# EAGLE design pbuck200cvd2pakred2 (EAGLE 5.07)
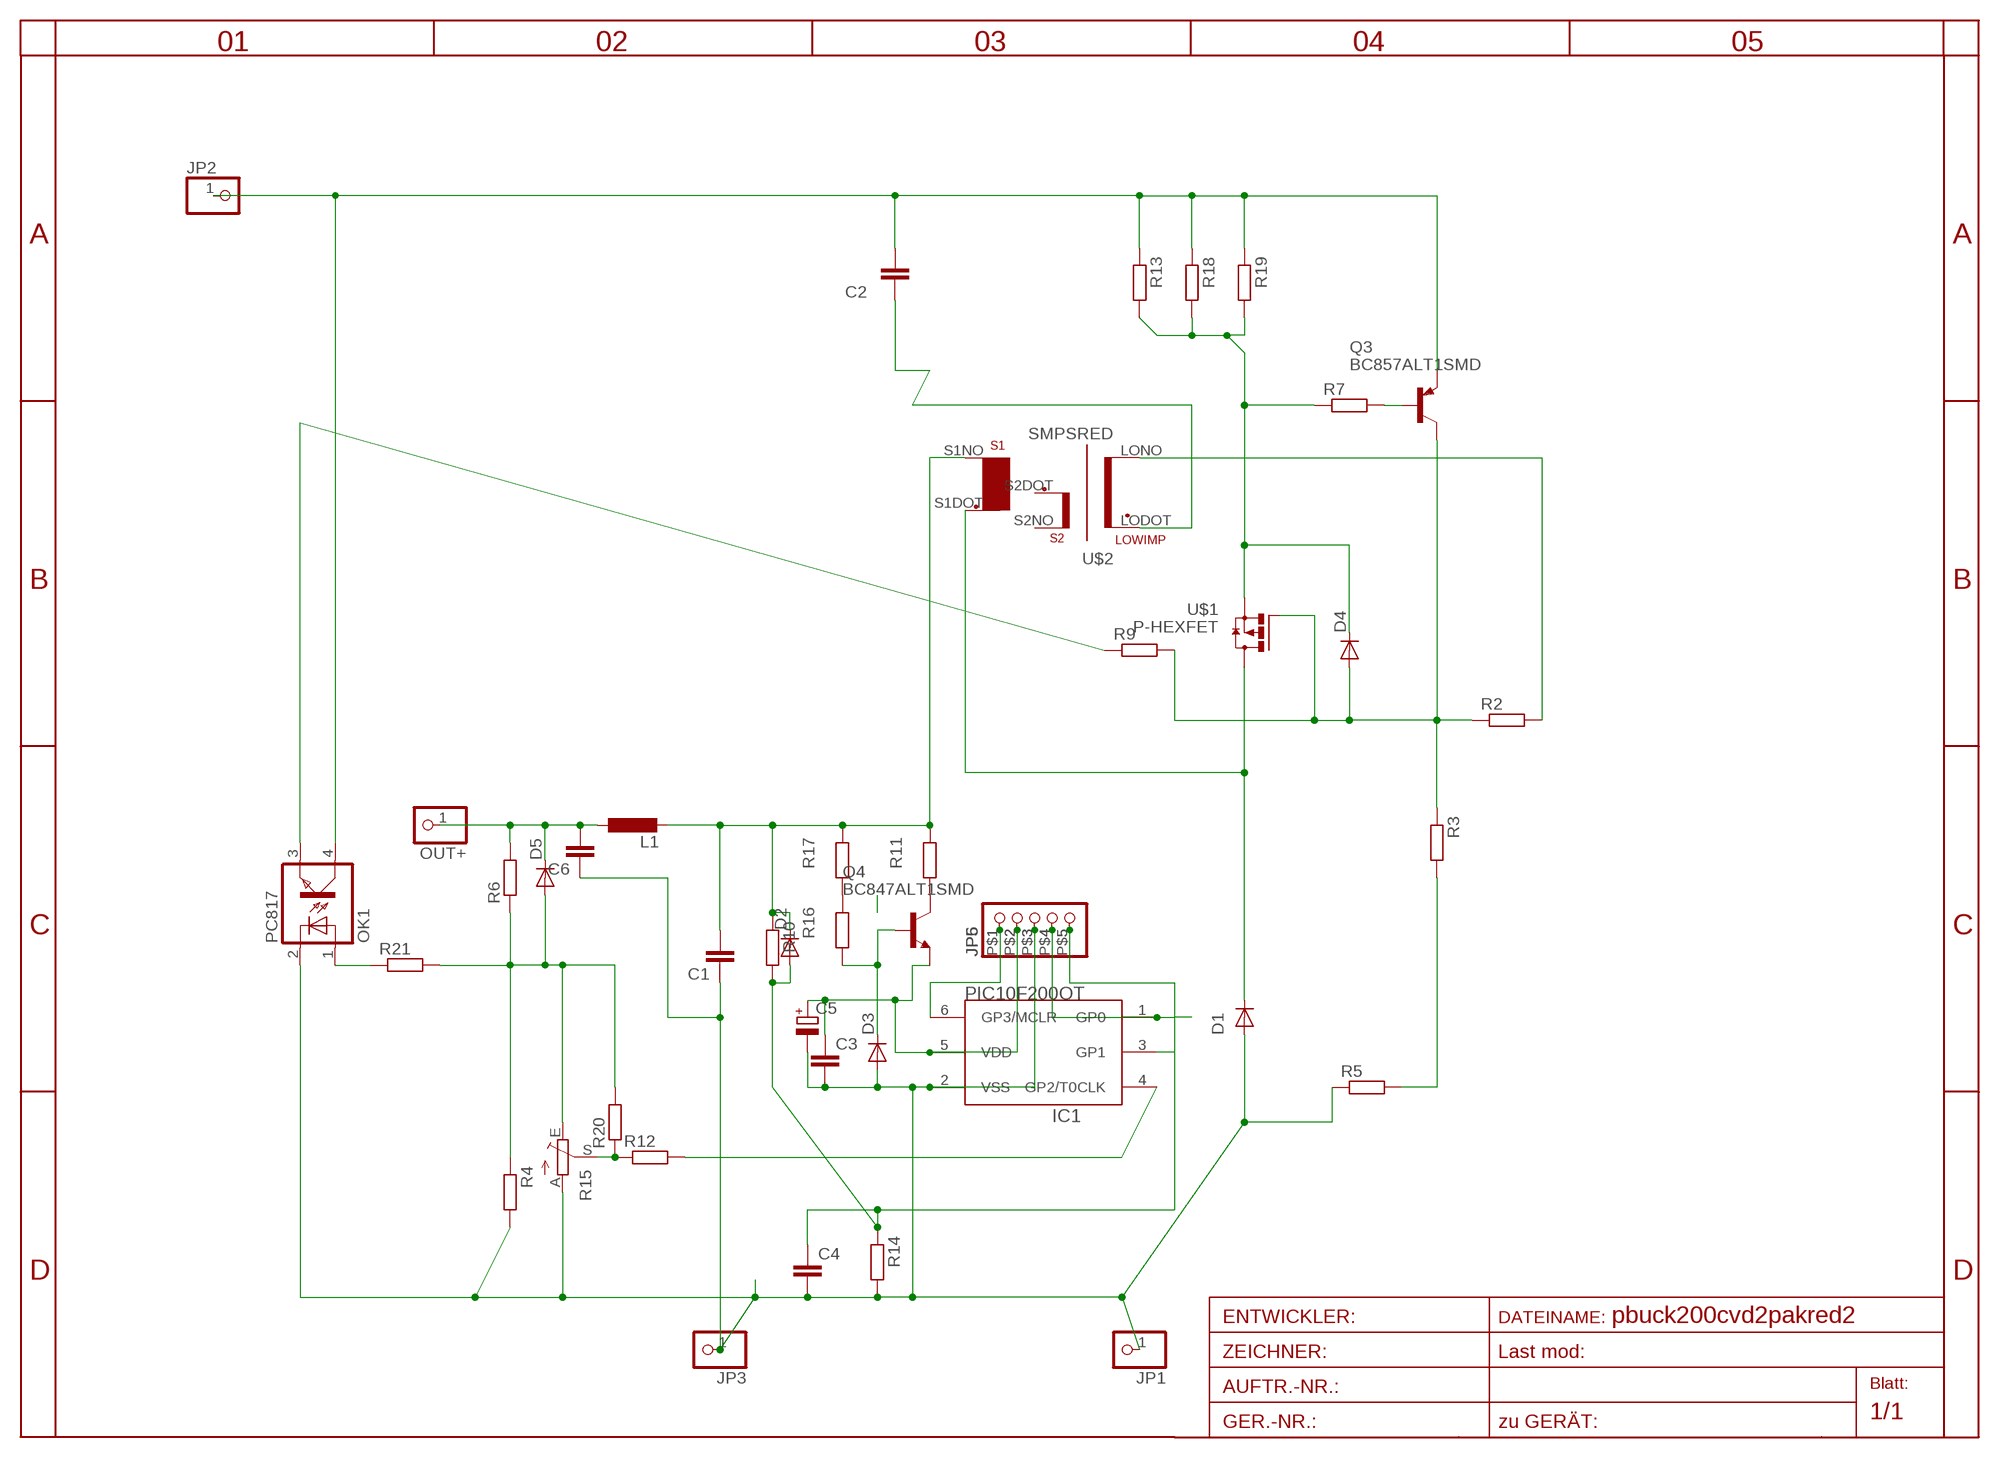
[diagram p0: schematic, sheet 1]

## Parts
C1  C-EU025-025X050  [C025-025X050]
C2  C-EUC0805  [C0805]
C3  C-EUC0805  [C0805]
C4  C-EUC0805  [C0805]
C5  CPOL-EUSMCA  [SMC_A]
C6  C-EU025-025X050  [C025-025X050]
D1  DIODE-SMC  [SMC]
D2  DIODE-MINIMELF  [MINIMELF]
D3  DIODE-MINIMELF  [MINIMELF]
D4  DIODE-MINIMELF  [MINIMELF]
D5  DIODE-MINIMELF  [MINIMELF]
IC1  PIC10F200OT  [SOT23-6]
JP1  PINHD-1X11MM6  [1X1MM8]
JP2  PINHD-1X11MM6  [1X1MM8]
JP3  PINHD-1X11MM6  [1X1MM8]
JP5  PINHD-1X5  [1X05SMD]
JP6  PINHD-1X5/90  [1X05/90]
L1  L-EUOPEN  [OPEN5]
OK1  PC817  [DIL04]
OUT+  PINHD-1X11MM6  [1X1MM8]
Q3  BC857ALT1SMD  [SOT23-BEC]
Q4  BC847ALT1SMD  [SOT23]
R2  R-EU_R0805  [R0805]
R3  R-EU_R1206  [R1206]
R4  R-EU_R0805  [R0805]
R5  R-EU_R1206  [R1206]
R6  R-EU_R1206  [R1206]
R7  R-EU_R1206  [R1206]
R9  R-EU_R1206  [R1206]
R10  R-EU_R0805  [R0805]
R11  R-EU_R1206  [R1206]
R12  R-EU_R0805  [R0805]
R13  R-EU_R1206  [R1206]
R14  R-EU_R0805  [R0805]
R15  TRIM_EU-CA6V  [CA6V]
R16  R-EU_R1206  [R1206]
R17  R-EU_R1206  [R1206]
R18  R-EU_R3216  [R3216]
R19  R-EU_R2010  [R2010]
R20  R-EU_R0805  [R0805]
R21  R-EU_R0805  [R0805]
U$1  P-HEXFET  [D2PACK]
U$2  SMPSRED  [SMPS_R]

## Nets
-: C1.1 C3.2 C4.2 C5.- C6.1 D1.A D3.A IC1.2(VSS) JP1.1 JP3.1 JP5.P$3 JP6.3 OK1.2(C) R4.2 R5.1 R14.2 R15.A
B1C2: OK1.3(EMIT) R9.1
C1: D1.C U$1.2(D) U$2.S1DOT
EB: D4.C R7.1 R13.2 R18.2 R19.2 U$1.3(S)
N$1: R3.2 R5.2
N$2: D4.A Q3.C R2.1 R3.1 R9.2 U$1.1(G)
N$3: Q3.B R7.2
N$4: R2.2 U$2.LONO
N$5: Q4.3(C) R11.1
N$6: C2.1 U$2.LODOT
N$8: R12.1 R15.S R20.1
N$9: IC1.4(GP2/T0CLK) R12.2
N$10: D3.C Q4.1(B) R16.1
N$12: C4.1 D2.A IC1.1(GP0) JP5.P$4 JP6.4 R10.2 R14.1
N$13: R16.2 R17.1
N$14: D5.A R4.1 R6.1 R15.E R20.2 R21.2
N$15: C3.1 C5.+ IC1.5(VDD) JP5.P$2 JP6.2 Q4.2(E)
N$16: IC1.3(GP1) JP5.P$5 JP6.5
N$17: IC1.6(GP3/MCLR) JP5.P$1 JP6.1
N$18: OK1.1(A) R21.1
OUT: C6.2 D5.C L1.1 OUT+.1 R6.2
OUT+: C1.2 D2.C L1.2 R10.1 R11.2 R17.2 U$2.S1NO
VPLUS: C2.2 JP2.1 OK1.4(COL) Q3.E R13.1 R18.1 R19.1
Unconnected: U$2.S2DOT U$2.S2NO

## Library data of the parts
C1-C4 C6 = rcl:C-EU: CAPACITOR, European symbol
C5 = rcl:CPOL-EU: POLARIZED CAPACITOR, European symbol
D1-D5 = diode:DIODE-: DIODE
IC1 = microchip-5:PIC10F20*: uPC nW 0,25/0,5k Program Flash memory
JP1-JP3 OUT+ = pinhead:PINHD-1X1: PIN HEADER
JP5 JP6 = pinhead:PINHD-1X5: PIN HEADER
L1 = rcl:L-EU: INDUCTOR, European symbol
OK1 = optocoupler:PC817: SHARP OPTO COUPLER
Q3 = transistor-pnp:BC857*: PNP Transistror
Q4 = transistor-npn:BC847*: NPN Transistor
R2-R7 R9-R14 R16-R21 = rcl:R-EU_: RESISTOR, European symbol
R15 = pot:TRIM_EU-: POTENTIOMETER
U$1 = transistor-power:P-HEXFET
U$2 = trafo:SMPSRED

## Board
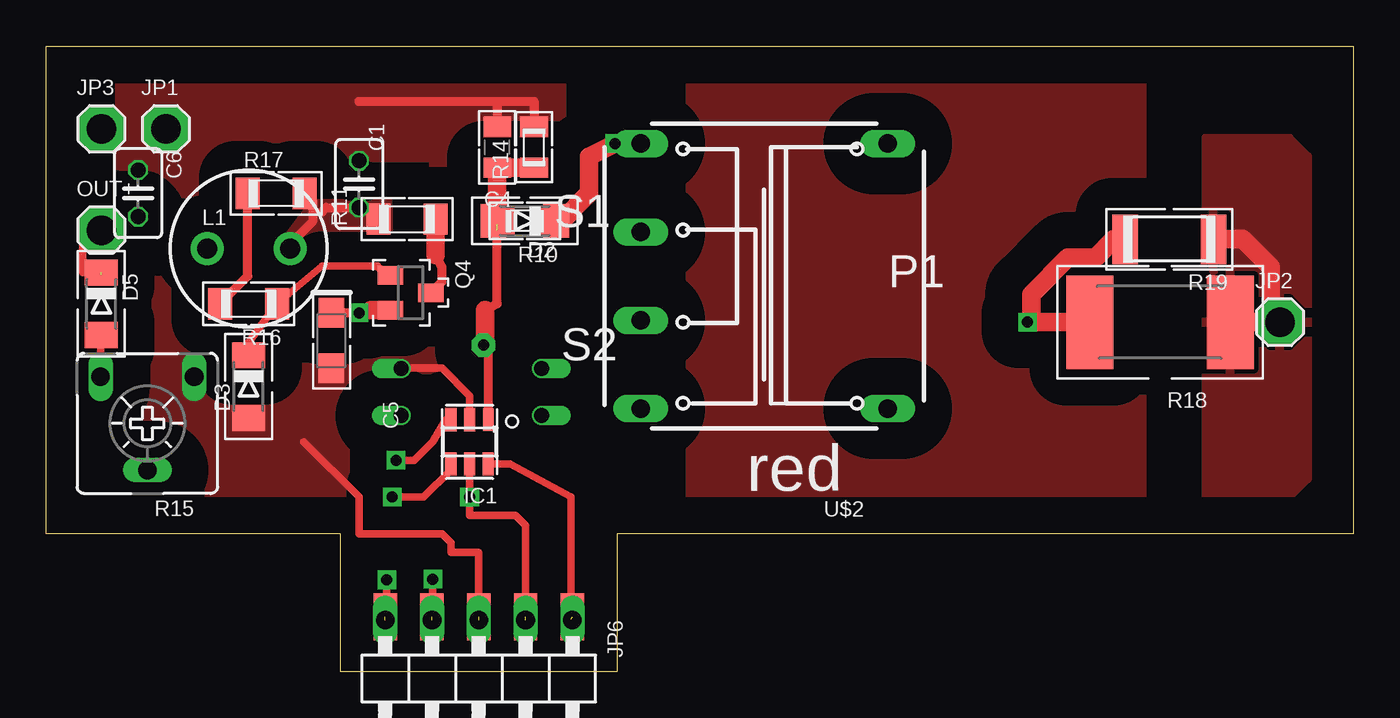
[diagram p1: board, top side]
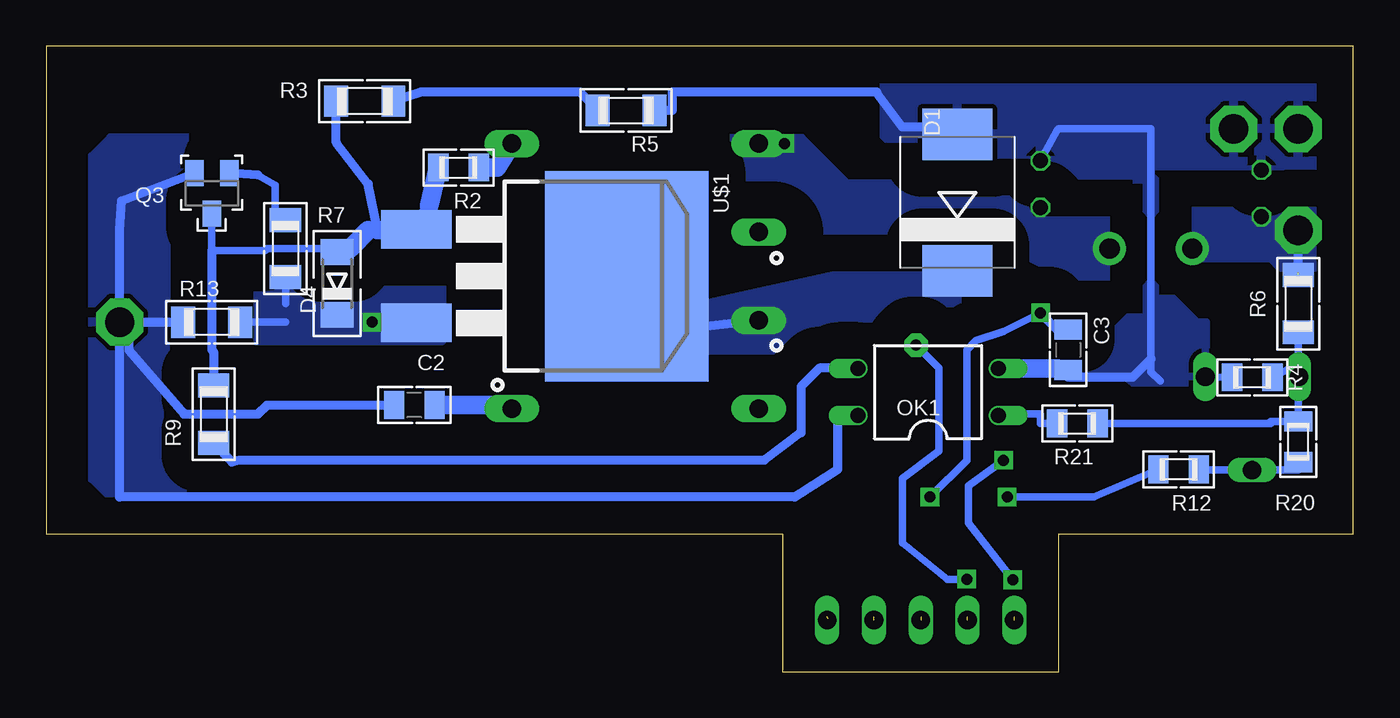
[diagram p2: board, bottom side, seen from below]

Size 71 x 34 mm. Coordinates in mm from the lower left corner, seen from the top.
Outline: 0,34 71,34 71,7.5 31,7.5 31,0 16,0 16,7.5 0,7.5 0,34
Copper layers (1*16): Top 0.035mm / dielectric 1.5mm / Bottom 0.035mm
Design rules "default *": minimum track width 10mil, minimum drill 20mil, track to track 8mil, track to pad 8mil, pad to pad 8mil, via to via 8mil, smd to smd 8mil, copper to edge 40mil, drill to drill 8mil, minimum pad ring 1mil, minimum via ring 8mil, stop-mask expansion 4mil, vias tented up to drill 0mil, thermal gap 10mil

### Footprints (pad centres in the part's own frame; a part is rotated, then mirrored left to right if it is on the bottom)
C025-025X050 = drill 0.813 octagon: 1 -1.27,0; 2 1.27,0
C0805 = smd 1.1 x 1.5: 1 -1.1,0; 2 1.1,0
SMC_A = smd 1.6 x 1.4: + -1.5,0; - 1.5,0
SMC = smd 2.8 x 3.8: A 3.7,0; C -3.7,0
MINIMELF = smd 1.4 x 1.8: A 1.7,0; C -1.7,0
SOT23-6 = smd 0.55 x 1.2: 1 -1.016,-1.2 | smd 0.6 x 1.27: 2 0,-1.2; 3 1.016,-1.2; 4 1.016,1.2; 5 0,1.2; 6 -1.016,1.2
1X1MM8 = drill 1.6 pad 2.54 octagon: 1 0,0
1X05SMD = smd 1.27 x 2.54: P$1 -5.08,0; P$2 -2.54,0; P$3 0,0; P$4 2.54,0; P$5 5.08,0
1X05/90 = drill 1.016 long: 1 -5.08,-3.81; 2 -2.54,-3.81; 3 0,-3.81; 4 2.54,-3.81; 5 5.08,-3.81
OPEN5 = drill 1.1 pad 1.778 round: 1 -2.25,0; 2 2.25,0
DIL04 = drill 0.813 offset: 1 -1.27,-3.81; 2 1.27,-3.81; 3 1.27,3.81; 4 -1.27,3.81
SOT23-BEC = smd 1 x 1.4: B -0.95,-1.1; C 0,1.1; E 0.95,-1.1
SOT23 = smd 1 x 1.4: 1 -0.95,-1.1; 2 0.95,-1.1; 3 0,1.1
R0805 = smd 1.1 x 1.5: 1 -1.1,0; 2 1.1,0
R1206 = smd 1.3 x 1.7: 1 -1.55,0; 2 1.55,0
CA6V = drill 1.016 long: A -2.54,-2.54; E 2.54,-2.54; S 0,2.54
R3216 = smd 2.54 x 5.08: 1 -3.81,0; 2 3.81,0
R2010 = smd 1.4 x 2.7: 1 -2.4,0; 2 2.4,0
D2PACK = smd 2.083 x 3.81: 1 -2.54,-8.89; 3 2.54,-8.89 | smd 11.43 x 8.89: 2 0,2.54
SMPS_R = drill 1 pad 1.5 long: LODOT 6.7,-7.2; LONO 6.7,7.2; S1DOT -6.7,-2.4; S1NO -6.7,7.2; S2DOT -6.7,2.4; S2NO -6.7,-7.2

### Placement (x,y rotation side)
C1  17,26.5 270 top
C2  51,14.5 180 bottom
C3  15.5,17.5 270 bottom
C4  24.5,28.5 90 top
C5  15.5,18 270 top
C6  5,26 270 top
D1  21.5,25.5 90 bottom
D2  26,24.5 180 top
D3  11,15.5 270 top
D4  55.2,21.1 90 bottom
D5  3,20 270 top
IC1  23,12.5 180 top
JP1  6.5,29.5 0 top
JP2  67,19 0 top
JP3  3,29.5 0 top
JP5  23.5,3 180 top
JP6  23.5,-1 180 top
L1  11,23 0 top
OK1  23.1,15.2 90 bottom
OUT+  3,24 0 top
Q3  62,26 180 bottom
Q4  19.8,20.6 270 top
R2  48.6,27.4 0 bottom
R3  53.69,31 0 bottom
R4  5.5,16 180 bottom
R5  39.5,30.5 180 bottom
R6  3,20 90 bottom
R7  58,23 90 bottom
R9  61.9,14 90 bottom
R10  26,24.5 180 top
R11  19.6,24.6 180 top
R12  9.5,11 180 bottom
R13  62,19 0 bottom
R14  26.5,28.5 90 top
R15  5.5,13.5 180 top
R16  11,20 180 top
R17  12.5,26 0 top
R18  60.5,19 180 top
R19  61,23.5 180 top
R20  3,12.5 90 bottom
R21  15,13.5 0 bottom
U$1  42,21.5 270 bottom
U$2  39,21.5 0 top

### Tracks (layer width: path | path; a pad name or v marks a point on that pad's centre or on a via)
-  (1 unrouted)
  Top 0.406: IC1.2 23,15 21.5,16.5 19.32,16.5 OK1.2 | JP5.P$3 23.5,6.5 22,6.5 22,7 21.5,7.5 17,7.5 17,9.5 14,12.5
  Top 0.5: C4.2 24.5,31 19,31 | R14.2 26.5,31 17,31
  Bottom 0.406: R4.2 8.06,16.04 R15.A | OK1.2 19.32,16.5 | C1.1 16.1,29.4 16,29.5 11,29.5 11,17 11,16.3 10.5,15.8
  Bottom 0.5: R5.1 37,30.5 37,31.5 25.9,31.5 C4.2 21.9,29.6 D1.A | 16.57,16.47 16,16.43 C3.2 15.9,16.4 15.5,16 12,16 11,17
  Bottom 1: OK1.2 16.04,16.47 16,16.43
  pour Bottom (isolate 2, rank 2): 1.5,32 25.5,32 25.5,26.5 1.5,26.5
  pour Top (isolate 2, rank 3, no thermals): 4,32 28,32 28,25.5 25,23 25,8 4,8.5
  pour Bottom (isolate 1.778, rank 2): 18.5,15.5 8,15.5 8,19 8.5,19 10.5,21 10.5,26.5 11,27 11.5,27 12,26.5 12,19.5 14,17.5 18,17.5 18.5,17
B1C2
  Bottom 0.5: R9.1 60.9,11.4 60.5,11.5 32,11.5 30,13 30,15.5 29,16.5 26.94,16.5 OK1.3
C1
  Bottom 0.5: U$2.S1DOT 36.56,18.6 U$1.2
  pour Bottom (isolate 2, rank 2, no thermals): 21.5,23 35,20 37,17.5 21.5,17.5
EB  (via drill 0.6)
  Top 1: v53.3,19 53.5,19 | 53.5,19 R18.2 | R19.2 58,23.5 57,22.5 55.5,22.5 53.5,20.5 53.5,19
  Bottom 0.406: 58,20 R7.1 | 58,19 R13.2
  Bottom 1: v53.3,19 50.93,19 U$1.3
  pour Bottom (isolate 2, rank 2, no thermals): 49.5,18 49.5,21 61.5,21 61.5,18
N$1
  Bottom 0.5: R5.2 41.05,30.55 42,31.5 50.64,31.5 R3.2
N$2
  Bottom 0.406: Q3.C 62,22.9 59.1,22.9 59,23 54.8,23 D4.A 54.5,23 | 53,24 53.5,24 | 51.5,24 50.93,24 U$1.1
  Bottom 0.5: R3.1 55.24,28.76 53.5,26.5 53,24 | R9.2 61.9,17.4 62,17.5 62,22.9 | 51.5,24 50.2,25.3
  Bottom 1: 53.5,24 54.5,23 | 51.5,24 53,24 | 50.2,25.3 R2.1
N$3
  Bottom 0.406: 59.5,27 58.55,26.45 58.55,25.1 R7.2
  Bottom 0.5: 59.5,27 Q3.B
N$4
  Bottom 1: R2.2 46.5,27.4 U$2.LONO
N$5
  Top 0.5: 21.15,22.65 21.5,22 21.5,21.2 Q4.3
  Top 1: 21.15,22.65 R11.1
N$6
  Bottom 0.5: U$2.LODOT 45.9,14.5
  Bottom 1: 45.9,14.5 C2.1
N$8
  Bottom 0.406: R12.1 8.36,10.96 R15.S 3,10.96 R20.1
N$9  (via drill 0.6)
  Top 0.406: IC1.4 21.98,10.98 20.5,9.5 v18.8,9.5
  Bottom 0.406: v18.8,9.5 14.1,9.5 R12.2
N$10
  Top 0.406: D3.C 10.9,17.75 R16.1 15,22.05 18,22.05 18,22 Q4.1
N$12  (via drill 0.6, 0.6 pad 1.27)  (2 unrouted)
  Top 0.406: JP5.P$4 v21,5.04 | 24.5,24.3 24.7,24.3 R10.2 | v23.75,17.75 23.85,17.75
  Top 0.5: IC1.1 24.02,17.48 v23.75,17.75 | 23.85,19.65 24.5,20 24.5,24 | D2.A 24.5,24.3
  Top 1: 23.85,17.75 23.85,19.65 | R14.1 C4.1 24.5,24.7 D2.A
  Bottom 0.406: v21,5.04 22.04,5.04 24.5,7 24.5,10.5 22.5,12 22.5,16.5 v23.75,17.75
N$13
  Top 0.5: R17.1 10.95,21.5 R16.2
N$14
  Top 0.406: D5.A 2.96,18.3 R15.E
  Bottom 0.406: R6.1 3,16.08 R15.E | R4.1 3.42,16.5 R15.E | R15.E 3,16.04 R20.2 4.5,13.6 4.5,13.5 R21.2
N$15  (via drill 0.6)  (1 unrouted)
  Top 0.406: JP5.P$2 26.04,7.96 25.5,8.5 23,8.5 v23,9.5 IC1.5 | v17,19.5 17.65,19.65
  Top 0.5: v17,19.5 C5.+
  Top 1: 17.65,19.65 Q4.2
  Bottom 0.406: v17,19.5 19,18.5 20.5,18 21,17.5 21,11.5 v23,9.5
  Bottom 0.5: C3.1 16.1,18.6 v17,19.5
N$16  (via drill 0.6)  (1 unrouted)
  Top 0.406: IC1.3 21.7,13.7 21,12.5 20,11.5 v19,11.5 | JP6.5 18.5,2.81 v18.5,5
  Bottom 0.406: v19,11.5 20.9,10.1 20.9,8.1 v18.5,5
N$17  (1 unrouted)
  Top 0.406: IC1.6 25.2,11.3 28.5,9.5 28.5,2.89 JP6.1
N$18
  Bottom 0.406: R21.1 17,13.5 17,14 19.29,14 OK1.1
N$19
  pour Top (isolate 2, rank 5): 35,32.5 59.5,32.5 59.5,8.5 35,8.5
OUT  (1 unrouted)
  Top 0.406: D5.C 2,21.7 2,24
  Bottom 0.5: R6.2 OUT+.1
  pour Bottom (isolate 2, no thermals): 2,25 9.5,25 9.5,22.5 4.5,22.5 4,22 2,22
OUT+  (via drill 0.6)
  Top 0.406: C1.2 R11.2 | D2.C R10.1
  Top 0.5: L1.2 13.25,23.25 14.5,24.5 14.5,25.55 R17.2 | C1.2 15.23,25.23 15,25
  Top 1: D2.C 28,24.5 29.5,26 29.5,28 v30.9,28.7
  Bottom 1: v30.9,28.7 U$2.S1NO
  pour Bottom (isolate 2, no thermals): 30,29 34,29 34,25.5 31,24 20.5,24 15.5,21.5 12.5,21.5 12.5,24.5 17.5,24.5 18.5,26.5 27.5,26.5
  pour Top (isolate 1.676, rank 2, no thermals): 14.5,25.5 19,25.5 19,23.5 13,23.5
VPLUS
  Top 1: JP2.1 66.5,19 | 66.5,19 R18.1 | R19.1 65,23.5 66.5,22 66.5,19
  Bottom 0.5: 67,18.5 JP2.1 | 67,18.5 67,9.5 30.34,9.5 28,11 28,13.93 OK1.4 | Q3.E 66.9,25.6 67,24 JP2.1 | JP2.1 R13.1 | C2.2 59,14.5 59.5,14 63.5,14 66.5,17.5 66.5,18 67,18.5
  pour Top (isolate 2, rank 4): 63,29 67.5,29 68.5,28 68.5,10.5 67.5,9.5 63,9.5 63,28.5
  pour Bottom (isolate 2, rank 4): 63,29 67.5,29 68.5,28 68.5,10.5 67.5,9.5 63,9.5 63,28.5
